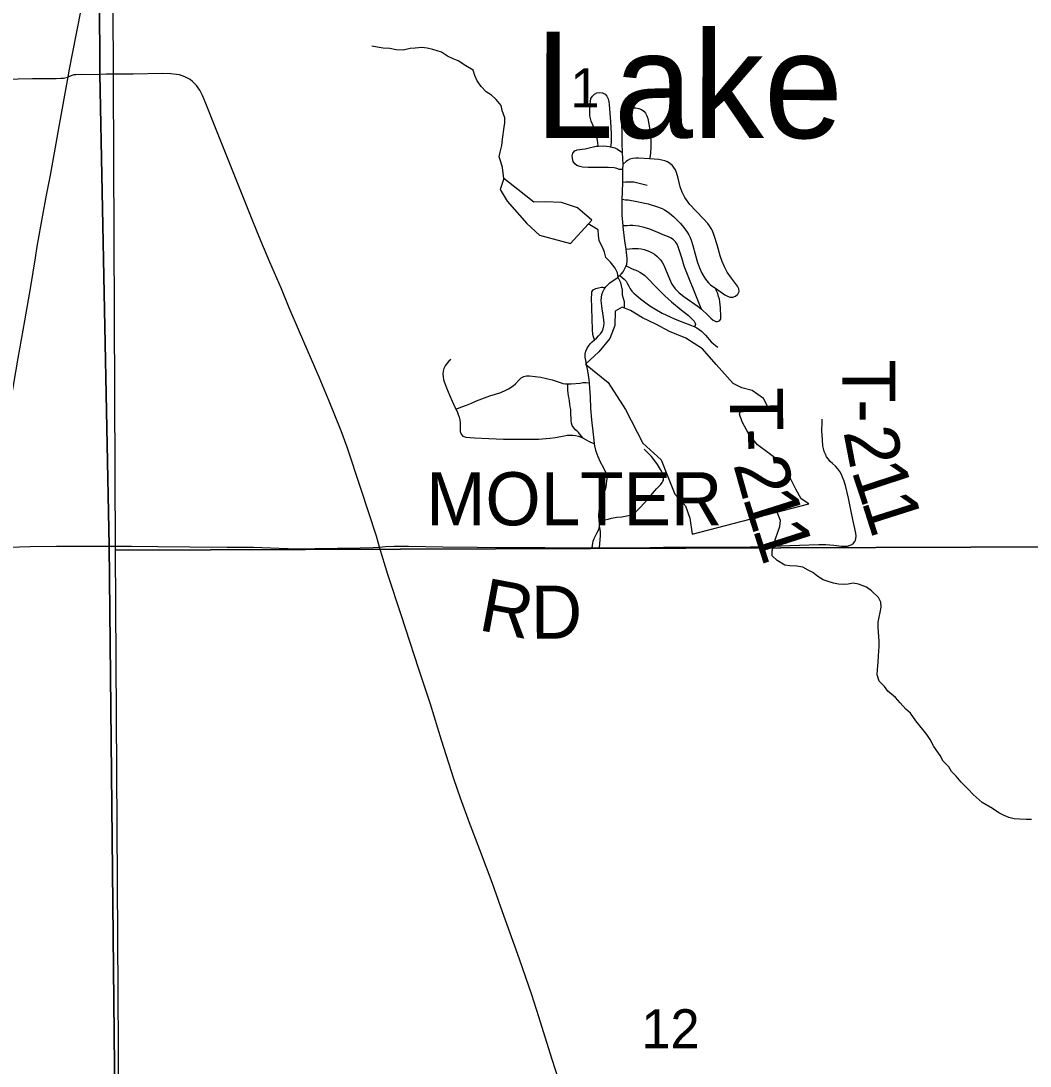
# Model space of a CAD drawing. Extents: x 0 to 34, y 0 to 22.
# Drawn here: x 2.529 to 3.608, y 16.821 to 17.938 of the extents above; entities that cross this region are included whole.
import ezdxf

# ---------------------------------------------------------------- set-up
doc = ezdxf.new("R2010")
doc.units = 0
for name, color, linetype in [('Default', 7, 'Continuous'), ('GM_X_County_Road', 7, 'Continuous'), ('GM_X_Minor_Lake', 7, 'Continuous'), ('GM_X_Minor_Lake_Text', 7, 'Continuous'), ('GM_X_Minor_River', 7, 'Continuous'), ('GM_X_Section', 7, 'Continuous'), ('GM_X_Section_Text', 7, 'Continuous'), ('GM_X_Township_Road', 7, 'Continuous'), ('GM_X_Township_Road_Text', 7, 'Continuous'), ('SH_Cut_Line', 7, 'Continuous')]:
    doc.layers.add(name, color=color, linetype=linetype)

msp = doc.modelspace()

# ---------------------------------------------------------------- linework, layer by layer
at = {"layer": 'Default'}
msp.add_lwpolyline([(2.1, 18.375), (2.1, 14.3539), (2.1651, 14.3567), (2.6607, 14.3625), (2.6434, 15.3487), (2.6428, 15.3713), (2.6388, 15.4856), (2.6332, 16.3685), (2.6231, 17.3771), (2.6129, 17.8818), (2.6122, 18.05), (2.6118, 18.3803)], close=True, dxfattribs=at)
msp.add_lwpolyline([(2.6122, 18.05), (2.6129, 17.8818), (2.6231, 17.3771), (2.6332, 16.3685)], dxfattribs=at)
at = {"layer": 'GM_X_County_Road'}
for points in [[(2.5792, 17.8787), (2.5807, 17.8867), (2.5876, 17.9233), (2.6008, 17.9904), (2.6124, 18.0495)], [(2.1338, 17.8727), (2.143, 17.873), (2.1679, 17.8731), (2.2021, 17.8734), (2.2332, 17.8737), (2.2706, 17.8742), (2.3017, 17.8749), (2.3328, 17.8752), (2.3483, 17.8753), (2.3639, 17.8754), (2.3825, 17.8755), (2.4074, 17.8755), (2.4447, 17.8757), (2.4883, 17.8761), (2.5256, 17.8767), (2.5411, 17.8769), (2.5661, 17.877), (2.5714, 17.8773), (2.5741, 17.8774), (2.5755, 17.8776), (2.5786, 17.8784), (2.5792, 17.8787)], [(2.4906, 17.3748), (2.5032, 17.4493), (2.507, 17.4707), (2.5177, 17.5319), (2.5258, 17.5778), (2.5327, 17.6176), (2.5393, 17.6543), (2.5418, 17.6697), (2.5441, 17.685), (2.546, 17.6973), (2.5521, 17.7309), (2.5561, 17.7522), (2.5601, 17.7736), (2.5662, 17.8072), (2.5695, 17.8255), (2.5792, 17.8787)], [(2.5792, 17.8787), (2.5833, 17.8803), (2.5857, 17.881), (2.5873, 17.8812), (2.5933, 17.8814), (2.6131, 17.8812)]]:
    msp.add_lwpolyline(points, dxfattribs=at)
at = {"layer": 'GM_X_Minor_Lake'}
for points in [[(3.139, 17.7255), (3.1238, 17.7387), (3.1067, 17.7444), (3.0893, 17.7451), (3.0772, 17.7447), (3.0601, 17.7583), (3.0449, 17.77), (3.0412, 17.7582), (3.0484, 17.7457), (3.0697, 17.7219), (3.083, 17.7094), (3.1164, 17.7004)], [(3.1164, 17.7004), (3.139, 17.7255)], [(3.3712, 17.4219), (3.3629, 17.4272), (3.3572, 17.4378), (3.3499, 17.4526), (3.3415, 17.4662), (3.3286, 17.476), (3.3161, 17.4851), (3.3069, 17.4964), (3.2997, 17.5097), (3.297, 17.518), (3.2996, 17.5256), (3.3098, 17.5264), (3.3197, 17.5238), (3.3273, 17.5257), (3.3227, 17.5348), (3.3105, 17.5431), (3.2995, 17.5461), (3.2904, 17.5507), (3.2722, 17.5711), (3.2573, 17.5878), (3.2395, 17.5991), (3.222, 17.6062), (3.2076, 17.6142), (3.1932, 17.6209), (3.1803, 17.6289), (3.1716, 17.6323), (3.164, 17.6281), (3.1637, 17.6129), (3.1584, 17.5988), (3.1467, 17.5847), (3.1324, 17.5714), (3.1567, 17.5517), (3.175, 17.523), (3.1937, 17.487), (3.2131, 17.4692), (3.22, 17.4518), (3.228, 17.4324), (3.2394, 17.4199), (3.244, 17.4067), (3.2464, 17.3896)], [(3.2464, 17.3896), (3.3712, 17.4219)]]:
    msp.add_lwpolyline(points, dxfattribs=at)
at = {"layer": 'GM_X_Minor_River'}
for points in [[(2.9961, 17.8958), (2.9908, 17.8981), (2.9847, 17.9007), (2.9782, 17.9049), (2.969, 17.908), (2.9629, 17.9095), (2.9572, 17.9099), (2.9503, 17.9095), (2.945, 17.9091), (2.9373, 17.9072), (2.9297, 17.9076), (2.9232, 17.9088), (2.916, 17.9095), (2.9095, 17.9103), (2.9037, 17.9114)], [(3.0449, 17.77), (3.0437, 17.7817), (3.0418, 17.7878), (3.0399, 17.7931), (3.041, 17.798), (3.0429, 17.8053), (3.0437, 17.8121), (3.0455, 17.8247), (3.0459, 17.8296), (3.0459, 17.8349), (3.0432, 17.8425), (3.042, 17.8479), (3.0367, 17.8543), (3.0317, 17.8589), (3.026, 17.8627), (3.0206, 17.8684), (3.0164, 17.8745), (3.0141, 17.8802), (3.0122, 17.8859), (3.0045, 17.8905), (2.9961, 17.8958)], [(3.174, 17.6313), (3.1742, 17.6379), (3.1719, 17.6451), (3.1719, 17.6504), (3.17, 17.6584), (3.1673, 17.6641), (3.1665, 17.6691), (3.1642, 17.674), (3.1592, 17.6805), (3.1542, 17.6854), (3.1527, 17.6911), (3.1504, 17.6964), (3.147, 17.7033), (3.1462, 17.7094), (3.1458, 17.7151), (3.1353, 17.7214)], [(3.3703, 17.3511), (3.3646, 17.3541), (3.3584, 17.3552), (3.3508, 17.3556), (3.3455, 17.3564), (3.3374, 17.3613), (3.3321, 17.3663), (3.3321, 17.3716), (3.3336, 17.3781), (3.3355, 17.3845), (3.3381, 17.3918), (3.34, 17.3978), (3.3408, 17.4043), (3.3374, 17.4131)], [(3.6091, 17.0844), (3.6037, 17.0844), (3.5965, 17.0848), (3.5907, 17.0851), (3.585, 17.0867), (3.58, 17.0886), (3.5743, 17.0916), (3.5674, 17.0962), (3.5564, 17.1026), (3.5468, 17.111), (3.5414, 17.1167), (3.5342, 17.1243), (3.5288, 17.1308), (3.5238, 17.1357), (3.5208, 17.1407), (3.5147, 17.1468), (3.5116, 17.1529), (3.5047, 17.1624), (3.5009, 17.17), (3.4974, 17.1753), (3.4855, 17.1898), (3.4798, 17.1981), (3.4748, 17.2023), (3.4687, 17.2092), (3.4637, 17.2149), (3.4557, 17.2217), (3.4519, 17.2267), (3.4465, 17.2324), (3.4442, 17.2392), (3.4446, 17.2449), (3.4453, 17.2525), (3.4457, 17.2594), (3.4464, 17.2696), (3.4464, 17.2753), (3.4456, 17.2848), (3.4452, 17.2902), (3.4452, 17.2955), (3.4464, 17.3008), (3.4475, 17.3058), (3.4486, 17.3115), (3.4482, 17.3168), (3.4455, 17.3217), (3.4383, 17.329), (3.4329, 17.3328), (3.4241, 17.3362), (3.4184, 17.337), (3.4131, 17.3362), (3.4077, 17.3358), (3.4028, 17.3362), (3.3974, 17.337), (3.3917, 17.3389), (3.3863, 17.3408), (3.3806, 17.3442), (3.3753, 17.3484), (3.3703, 17.3511)]]:
    msp.add_lwpolyline(points, dxfattribs=at)
at = {"layer": 'GM_X_Section'}
for points in [[(2.6434, 18.3786), (3.6306, 18.3893), (3.6458, 17.376), (2.6299, 17.3724), (2.6253, 18.3786)], [(2.6299, 17.3724), (3.6458, 17.376), (3.6462, 17.3555), (3.6522, 16.3668), (3.3278, 16.3702), (3.1951, 16.3831), (2.6357, 16.367)]]:
    msp.add_lwpolyline(points, close=True, dxfattribs=at)
at = {"layer": 'GM_X_Township_Road'}
for points in [[(2.9122, 17.3757), (2.9087, 17.3875), (2.8922, 17.4384), (2.8774, 17.4826), (2.871, 17.5001), (2.8583, 17.5319), (2.8474, 17.5576), (2.8266, 17.6061), (2.8156, 17.6318), (2.8071, 17.6518), (2.7948, 17.6803), (2.7851, 17.7032), (2.7758, 17.7262), (2.7573, 17.7723), (2.7366, 17.8243), (2.7264, 17.8503), (2.7227, 17.8588), (2.7198, 17.8643), (2.7181, 17.867), (2.7163, 17.8694), (2.7142, 17.8717), (2.7119, 17.8738), (2.7094, 17.8757), (2.7068, 17.8774), (2.704, 17.8788), (2.7011, 17.8799), (2.6981, 17.8807), (2.6951, 17.8813), (2.6889, 17.8819), (2.6796, 17.8821), (2.6485, 17.8817), (2.6197, 17.8814), (2.6131, 17.8812)], [(3.1459, 17.8047), (3.1454, 17.8081), (3.145, 17.8111), (3.1444, 17.8141), (3.1431, 17.8199), (3.1422, 17.8227), (3.141, 17.8255), (3.1384, 17.8311), (3.1375, 17.834), (3.137, 17.837), (3.1369, 17.8401), (3.137, 17.8432), (3.1373, 17.8493), (3.1375, 17.8524), (3.1382, 17.8554), (3.1397, 17.8581), (3.1418, 17.8602), (3.1446, 17.8614), (3.1476, 17.8618), (3.1505, 17.8614), (3.1532, 17.8601), (3.1552, 17.8579), (3.1565, 17.8551), (3.1573, 17.8521), (3.1576, 17.849), (3.1583, 17.8397), (3.1589, 17.8304), (3.1597, 17.818), (3.1598, 17.8087), (3.1594, 17.8057), (3.1592, 17.8039)], [(3.1474, 17.375), (3.1477, 17.3796), (3.1483, 17.3878), (3.1483, 17.3921), (3.148, 17.3946), (3.1474, 17.3982), (3.1472, 17.4022), (3.1471, 17.4036), (3.1468, 17.4059), (3.1466, 17.4078), (3.1466, 17.4107), (3.1468, 17.4136), (3.1478, 17.4196), (3.149, 17.4239), (3.1505, 17.4284), (3.1526, 17.4343), (3.1543, 17.4403), (3.1549, 17.4433), (3.1553, 17.4464), (3.1554, 17.4495), (3.155, 17.4525), (3.1541, 17.4555), (3.1514, 17.461), (3.1485, 17.4665), (3.1459, 17.4721), (3.1438, 17.478), (3.1423, 17.484), (3.142, 17.4863), (3.1415, 17.4901), (3.1404, 17.4993), (3.1391, 17.5117), (3.1382, 17.5241), (3.1377, 17.5365), (3.137, 17.5457), (3.1365, 17.5513), (3.1361, 17.5549), (3.1349, 17.5641), (3.1319, 17.579), (3.1318, 17.5821), (3.1325, 17.5851), (3.1337, 17.5879), (3.1354, 17.5906), (3.1373, 17.593), (3.1394, 17.5952), (3.1418, 17.5973), (3.1441, 17.5993), (3.1463, 17.6015), (3.1483, 17.6038), (3.15, 17.6064), (3.1512, 17.6093), (3.152, 17.6123), (3.1522, 17.6154), (3.152, 17.6183), (3.1516, 17.6212), (3.15, 17.6304), (3.1493, 17.6365), (3.1492, 17.6396), (3.1494, 17.6427), (3.1499, 17.6458), (3.1508, 17.6487), (3.1522, 17.6515), (3.1533, 17.6531), (3.154, 17.654), (3.1561, 17.6562), (3.1585, 17.6582), (3.1661, 17.6637), (3.1684, 17.6657), (3.1689, 17.6661), (3.1706, 17.6678), (3.1725, 17.6703), (3.1741, 17.6729), (3.1755, 17.6757), (3.1759, 17.6766), (3.1766, 17.6785), (3.177, 17.6816), (3.177, 17.6847), (3.1763, 17.6908), (3.1758, 17.6943), (3.1744, 17.7031), (3.1727, 17.7184), (3.1726, 17.7192), (3.1717, 17.7308), (3.1715, 17.74), (3.1716, 17.7477), (3.1718, 17.7555), (3.1721, 17.7659), (3.1724, 17.7741), (3.1724, 17.7793), (3.1725, 17.7852), (3.1723, 17.7909), (3.172, 17.7979), (3.1717, 17.8076), (3.1714, 17.82), (3.1712, 17.8262), (3.1711, 17.8293), (3.1715, 17.8325), (3.1723, 17.8357), (3.1736, 17.8387), (3.1753, 17.8414), (3.1774, 17.8435), (3.1801, 17.8449), (3.1831, 17.8456), (3.1862, 17.8455), (3.1892, 17.8449), (3.1921, 17.8437), (3.1946, 17.842), (3.1966, 17.8397), (3.198, 17.8369), (3.1989, 17.834), (3.2001, 17.828), (3.2011, 17.8219), (3.2019, 17.8158), (3.2022, 17.8096), (3.2022, 17.8034), (3.2017, 17.7974), (3.2013, 17.7943), (3.2008, 17.7908)], [(3.1724, 17.7793), (3.1717, 17.7794), (3.1688, 17.7797), (3.1658, 17.7806), (3.1628, 17.7812), (3.1567, 17.7818), (3.1444, 17.7816), (3.1352, 17.7816), (3.1291, 17.7822), (3.1261, 17.7828), (3.1232, 17.7838), (3.1208, 17.7857), (3.1192, 17.7883), (3.1183, 17.7912), (3.1182, 17.7942), (3.1189, 17.7972), (3.1208, 17.7995), (3.1235, 17.8006), (3.1263, 17.801), (3.1289, 17.8013), (3.1319, 17.8018), (3.1348, 17.8024), (3.1378, 17.8031), (3.1407, 17.8038), (3.1437, 17.8045), (3.1459, 17.8047), (3.1516, 17.8049), (3.1547, 17.8047), (3.1578, 17.8042), (3.1592, 17.8039), (3.1608, 17.8036), (3.1637, 17.8026), (3.1665, 17.8013), (3.1691, 17.7997), (3.172, 17.7979)], [(3.1716, 17.7477), (3.175, 17.7473), (3.1781, 17.747), (3.1873, 17.7454), (3.1994, 17.7427), (3.2084, 17.7399), (3.2142, 17.7377), (3.2169, 17.7363), (3.2196, 17.7347), (3.2221, 17.7329), (3.2269, 17.7289), (3.2335, 17.7222), (3.2375, 17.7175), (3.2411, 17.7124), (3.2427, 17.7097), (3.2441, 17.707), (3.2453, 17.7041), (3.2472, 17.6982), (3.2495, 17.6891), (3.252, 17.6801), (3.2541, 17.6743), (3.2567, 17.6686), (3.2598, 17.6632), (3.2617, 17.6607), (3.2638, 17.6584), (3.2661, 17.6563), (3.2685, 17.6544), (3.2714, 17.6525), (3.2763, 17.6491), (3.2813, 17.6455), (3.284, 17.644), (3.2869, 17.6431), (3.29, 17.6431), (3.2929, 17.6442), (3.2952, 17.6462), (3.2965, 17.649), (3.2962, 17.6521), (3.2947, 17.6548), (3.2872, 17.6647), (3.2838, 17.6699), (3.2809, 17.6755), (3.2785, 17.6812), (3.2764, 17.6871), (3.273, 17.699), (3.2703, 17.708), (3.268, 17.7138), (3.2666, 17.7165), (3.265, 17.7192), (3.2631, 17.7217), (3.259, 17.7264), (3.2502, 17.7352), (3.244, 17.7422), (3.2402, 17.7471), (3.2385, 17.7497), (3.2371, 17.7525), (3.2358, 17.7553), (3.2346, 17.7582), (3.2337, 17.7612), (3.2314, 17.7702), (3.2296, 17.7762), (3.2284, 17.7791), (3.2268, 17.7817), (3.2249, 17.7841), (3.2225, 17.7861), (3.2199, 17.7877), (3.217, 17.7889), (3.214, 17.7897), (3.2109, 17.7901), (3.2008, 17.7908), (3.1891, 17.7917), (3.186, 17.7917), (3.1829, 17.7915), (3.1799, 17.7907), (3.1772, 17.7893), (3.1757, 17.7881), (3.1725, 17.7852)], [(3.1721, 17.7659), (3.1751, 17.7662), (3.178, 17.7665), (3.181, 17.7665), (3.1839, 17.7662), (3.1896, 17.7651), (3.1981, 17.7628)], [(3.2563, 17.6301), (3.2553, 17.6326), (3.2482, 17.6504), (3.2436, 17.6618), (3.238, 17.6763), (3.2353, 17.6851), (3.2315, 17.6969), (3.2303, 17.6997), (3.2286, 17.7023), (3.2264, 17.7044), (3.2239, 17.7061), (3.2211, 17.7075), (3.2154, 17.7098), (3.2097, 17.7122), (3.2011, 17.7156), (3.1952, 17.7174), (3.1891, 17.7188), (3.183, 17.7195), (3.1799, 17.7195), (3.1768, 17.7194), (3.1726, 17.7192)], [(3.1758, 17.6943), (3.1795, 17.6947), (3.1825, 17.6951), (3.1857, 17.6952), (3.1888, 17.695), (3.1918, 17.6946), (3.1949, 17.6939), (3.1979, 17.693), (3.2008, 17.6919), (3.2036, 17.6905), (3.2062, 17.6889), (3.2087, 17.687), (3.2109, 17.6849), (3.2129, 17.6825), (3.2146, 17.6799), (3.216, 17.6771), (3.222, 17.6627), (3.2247, 17.6571), (3.2264, 17.6545), (3.2282, 17.652), (3.2303, 17.6497), (3.2325, 17.6475), (3.2374, 17.6436), (3.2527, 17.633), (3.2563, 17.6301), (3.2575, 17.6291), (3.262, 17.6247), (3.2665, 17.6204), (3.269, 17.6185), (3.2701, 17.6178), (3.2718, 17.6171), (3.2732, 17.617), (3.2747, 17.6172), (3.276, 17.6181), (3.2767, 17.6191), (3.277, 17.6201), (3.277, 17.6224), (3.2768, 17.6317), (3.2761, 17.6379), (3.2755, 17.6409), (3.2747, 17.6439), (3.2737, 17.6468), (3.2725, 17.6497), (3.2714, 17.6525)], [(3.1759, 17.6766), (3.1794, 17.6749), (3.1821, 17.6735), (3.1879, 17.6711), (3.1906, 17.6698), (3.1932, 17.6681), (3.1956, 17.6662), (3.2, 17.6619), (3.2064, 17.6553), (3.2173, 17.6443), (3.2242, 17.638), (3.2348, 17.6294), (3.2426, 17.6235), (3.2484, 17.6175), (3.2493, 17.6161), (3.2497, 17.6151), (3.2498, 17.614), (3.2497, 17.6131), (3.2494, 17.612), (3.2491, 17.6113)], [(3.1689, 17.6661), (3.1714, 17.6642), (3.1737, 17.6624), (3.1758, 17.6601), (3.1773, 17.6574), (3.1787, 17.6547), (3.1802, 17.652), (3.182, 17.6495), (3.1841, 17.6473), (3.1864, 17.6452), (3.1912, 17.6413), (3.2011, 17.6339), (3.2063, 17.6305), (3.2144, 17.626), (3.2227, 17.6219), (3.2283, 17.6195), (3.2456, 17.6129), (3.2491, 17.6113), (3.2512, 17.6103), (3.2538, 17.6086), (3.2563, 17.6068), (3.2586, 17.6047), (3.2607, 17.6025), (3.2667, 17.5954), (3.2689, 17.5933), (3.2713, 17.5913), (3.2739, 17.5897)], [(3.1418, 17.5973), (3.141, 17.6005), (3.1403, 17.6032), (3.1398, 17.6085), (3.1389, 17.6427), (3.1391, 17.6459), (3.1392, 17.6486), (3.1406, 17.6508), (3.1433, 17.6524), (3.1464, 17.6531), (3.1495, 17.6537), (3.1513, 17.6536), (3.1525, 17.6533), (3.1533, 17.6531)], [(2.9883, 17.5765), (2.9861, 17.5745), (2.984, 17.5721), (2.9822, 17.5696), (2.9808, 17.5669), (2.98, 17.5639), (2.9798, 17.5609), (2.98, 17.5578), (2.9806, 17.5548), (2.9815, 17.5519), (2.9837, 17.5461), (2.9873, 17.5374), (2.9898, 17.5318), (2.9938, 17.5234), (2.9951, 17.5206), (2.9962, 17.5177), (2.9971, 17.5148), (2.9979, 17.5117), (2.9984, 17.5087), (2.9984, 17.5056), (2.9982, 17.5025), (2.9983, 17.4994), (2.9992, 17.4965), (3.0013, 17.4943), (3.0043, 17.4933), (3.0136, 17.4925), (3.0291, 17.4918), (3.0446, 17.4913), (3.0695, 17.4911), (3.0819, 17.4913), (3.0943, 17.4922), (3.1004, 17.4929), (3.1095, 17.4948), (3.1126, 17.4953), (3.1157, 17.4956), (3.1188, 17.4956), (3.1218, 17.4951), (3.1247, 17.4943), (3.1276, 17.4933), (3.13, 17.4921), (3.133, 17.4905), (3.1357, 17.489), (3.1378, 17.4879), (3.1404, 17.4869), (3.142, 17.4863)], [(2.9938, 17.5234), (2.9999, 17.5256), (3.0051, 17.5277), (3.0104, 17.5298), (3.0158, 17.5321), (3.0215, 17.5343), (3.0272, 17.5365), (3.0301, 17.5375), (3.036, 17.5392), (3.0418, 17.5411), (3.0473, 17.5435), (3.05, 17.5449), (3.055, 17.5482), (3.0573, 17.5502), (3.0615, 17.5546), (3.0637, 17.5566), (3.0664, 17.5581), (3.0694, 17.5588), (3.0724, 17.5588), (3.0786, 17.5581), (3.0846, 17.5573), (3.0906, 17.5562), (3.0965, 17.5545), (3.1051, 17.5516), (3.108, 17.5508), (3.111, 17.5503), (3.1136, 17.5502), (3.1171, 17.5502), (3.1265, 17.5512), (3.1295, 17.5516), (3.1318, 17.5518), (3.1329, 17.5517), (3.1365, 17.5513)], [(3.13, 17.4921), (3.1259, 17.4969), (3.1252, 17.4978), (3.124, 17.4991), (3.1217, 17.501), (3.1197, 17.5032), (3.1181, 17.5057), (3.1173, 17.5084), (3.1169, 17.5113), (3.1168, 17.52), (3.1166, 17.5229), (3.1161, 17.5258), (3.1156, 17.5287), (3.1152, 17.5317), (3.1147, 17.5346), (3.1142, 17.5376), (3.1138, 17.5405), (3.1135, 17.5434), (3.1135, 17.5461), (3.1136, 17.5502)], [(3.4189, 17.3799), (3.4202, 17.3816), (3.4209, 17.3831), (3.4214, 17.3851), (3.4217, 17.3876), (3.4214, 17.3905), (3.4172, 17.4103), (3.4134, 17.4279), (3.4108, 17.4401), (3.409, 17.4462), (3.4073, 17.4505), (3.4059, 17.4535), (3.4042, 17.4565), (3.402, 17.4594), (3.3996, 17.4622), (3.3965, 17.4651), (3.394, 17.4674), (3.392, 17.4698), (3.3902, 17.4724), (3.3888, 17.4752), (3.3876, 17.4781), (3.3868, 17.4811), (3.3862, 17.4842), (3.3856, 17.4904), (3.3852, 17.4999), (3.3853, 17.5093), (3.3853, 17.5124)], [(3.1471, 17.4036), (3.1487, 17.404), (3.1525, 17.4049), (3.1564, 17.4057), (3.16, 17.4065), (3.1658, 17.4076), (3.1712, 17.4082), (3.1782, 17.4095), (3.1814, 17.4104), (3.1836, 17.4113), (3.1863, 17.4134), (3.1884, 17.4156), (3.1908, 17.418), (3.195, 17.4227), (3.1991, 17.427), (3.204, 17.4331), (3.2084, 17.4382), (3.2104, 17.4402), (3.2125, 17.4424), (3.2142, 17.4448), (3.2151, 17.4462), (3.2156, 17.4474), (3.2158, 17.4491), (3.2158, 17.4504), (3.2156, 17.4518), (3.2152, 17.4534), (3.214, 17.4563), (3.2125, 17.4589), (3.2092, 17.4642), (3.2066, 17.4681), (3.2028, 17.4727), (3.1951, 17.4805)], [(3.1395, 17.3751), (3.1398, 17.3775), (3.1401, 17.3799), (3.1406, 17.382), (3.1417, 17.3849), (3.1444, 17.3905), (3.1458, 17.3932), (3.1469, 17.3961), (3.1474, 17.3982)], [(2.4906, 17.3748), (2.4921, 17.3749), (2.5386, 17.3762), (2.5665, 17.3767), (2.6234, 17.3766)], [(2.6234, 17.3766), (2.647, 17.3767), (2.6749, 17.3763), (2.7091, 17.3759), (2.7491, 17.3756), (2.7774, 17.3756), (2.8045, 17.3747), (2.8244, 17.374), (2.843, 17.3742), (2.8913, 17.3748), (2.9054, 17.3752), (2.9122, 17.3757)], [(2.9122, 17.3757), (2.9184, 17.3762), (2.9277, 17.3767), (2.9431, 17.3767), (2.9797, 17.3759), (3.0164, 17.3755), (3.0582, 17.3754), (3.0888, 17.3753), (3.1243, 17.3751), (3.1395, 17.3751)], [(3.105, 16.8023), (3.0964, 16.8289), (3.0825, 16.8733), (3.075, 16.897), (3.0617, 16.9352), (3.0418, 16.9907), (3.0324, 17.0171), (3.0193, 17.0519), (3.0084, 17.081), (2.9986, 17.1072), (2.9916, 17.1278), (2.9783, 17.1692), (2.9664, 17.2078), (2.9539, 17.2462), (2.9354, 17.3022), (2.9211, 17.3466), (2.9122, 17.3757)], [(3.1395, 17.3751), (3.1474, 17.375), (3.154, 17.375), (3.1865, 17.3751), (3.2159, 17.3756), (3.2433, 17.3757), (3.268, 17.3756), (3.2946, 17.3757), (3.3228, 17.3764), (3.3508, 17.3773), (3.382, 17.3786), (3.3893, 17.3784), (3.398, 17.3777), (3.406, 17.3767), (3.4092, 17.3766), (3.4124, 17.3768), (3.4155, 17.3777), (3.4172, 17.3786), (3.4189, 17.3799)]]:
    msp.add_lwpolyline(points, dxfattribs=at)
at = {"layer": 'SH_Cut_Line'}
msp.add_lwpolyline([(2.6032, 20.9), (2.1, 20.9), (2.1, 14.3539), (2.1651, 14.3567), (2.6607, 14.3625), (2.6434, 15.3487), (2.6428, 15.3713), (2.6388, 15.4856), (2.6332, 16.3685), (2.6231, 17.3771), (2.6129, 17.8818), (2.6122, 18.05), (2.6118, 18.3803), (2.6161, 18.3799), (2.6204, 18.3797), (2.6263, 18.3795), (2.6292, 18.3794), (2.6281, 18.8843), (2.6224, 19.9515), (2.6032, 20.8721)], close=True, dxfattribs=at)
msp.add_lwpolyline([(8.9, 20.9), (2.6032, 20.9), (2.6032, 20.8721), (2.6224, 19.9515), (2.6281, 18.8843), (2.6292, 18.3794), (2.6263, 18.3795), (2.6204, 18.3797), (2.6161, 18.3799), (2.6118, 18.3803), (2.6122, 18.05), (2.6129, 17.8818), (2.6231, 17.3771), (2.6332, 16.3685)], dxfattribs=at)

# ---------------------------------------------------------------- texts
at = {"layer": 'GM_X_Minor_Lake_Text'}
msp.add_text('Lake', height=0.11366, rotation=359.9694, dxfattribs=at).set_placement((3.0781, 17.8133))
at = {"layer": 'GM_X_Section_Text'}
for s, height, p in [('1', 0.0419, (3.1162, 17.8459)), ('12', 0.04186, (3.1921, 16.8396))]:
    msp.add_text(s, height=height, rotation=0, dxfattribs=at).set_placement(p)
at = {"layer": 'GM_X_Township_Road_Text'}
for s, height, rotation, p in [('T', 0.0568, 269.8865, (3.407, 17.5766)), ('T', 0.0568, 270.1671, (3.2868, 17.5467)), ('-', 0.0568, 269.8865, (3.4069, 17.5341)), ('-', 0.0568, 272.2604, (3.287, 17.5019)), ('2', 0.0568, 280.9208, (3.408, 17.4992)), ('2', 0.0568, 285.7276, (3.2901, 17.4642)), ('1', 0.0568, 288.1948, (3.4165, 17.4575)), ('MOLTER', 0.05682, 0.0048, (2.962, 17.399)), ('1', 0.0568, 287.6169, (3.3002, 17.4286)), ('1', 0.0568, 287.6646, (3.4273, 17.4246)), ('1', 0.0568, 287.8008, (3.3109, 17.395)), ('R', 0.0568, 349.4353, (3.0165, 17.2872)), ('D', 0.0568, 0.4258, (3.0741, 17.2776))]:
    msp.add_text(s, height=height, rotation=rotation, dxfattribs=at).set_placement(p)

doc.saveas('drawing.dxf')
